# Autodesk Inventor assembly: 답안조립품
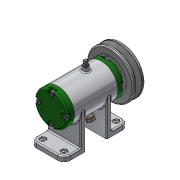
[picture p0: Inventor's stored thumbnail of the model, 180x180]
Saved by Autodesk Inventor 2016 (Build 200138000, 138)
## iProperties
Created: 2017-02
Part Number: 답안조립품
Material: 일반
Document SubType Name: Assembly
Designer: H
Author: H
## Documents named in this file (16)
- C:\Users\CAMTIC\Desktop\470207V1019\답안조립품.iam
- C:\Users\CAMTIC\Desktop\470207V1019\본체.ipt
- C:\Users\CAMTIC\Desktop\470207V1019\V벨트풀리.ipt
- C:\Users\CAMTIC\Desktop\470207V1019\너트 M 8.ipt
- C:\Users\CAMTIC\Desktop\470207V1019\니플 M 6 x 0.75.ipt
- C:\Users\CAMTIC\Desktop\470207V1019\뒤커버.ipt
- C:\Users\CAMTIC\Desktop\470207V1019\베어링 15 x 32 x 9.ipt
- C:\Users\CAMTIC\Desktop\470207V1019\볼트 M 6 x 8.ipt
- C:\Users\CAMTIC\Desktop\470207V1019\볼트 M4 x 12.ipt
- C:\Users\CAMTIC\Desktop\470207V1019\스프링와셔 8.ipt
- C:\Users\CAMTIC\Desktop\470207V1019\앞커버.ipt
- C:\Users\CAMTIC\Desktop\470207V1019\오일 실 15 25 7.ipt
- C:\Users\CAMTIC\Desktop\470207V1019\와셔 6x11.5.ipt
- C:\Users\CAMTIC\Desktop\470207V1019\와셔 8x17.ipt
- C:\Users\CAMTIC\Desktop\470207V1019\축.ipt
- C:\Users\CAMTIC\Desktop\470207V1019\키 3 x 3 x 12.ipt
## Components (11 placed, 3 different names)
1. V벨트풀리:1
2. KS B 2023 6002 - 15 x 32 x 9:1
3. KS B 2023 6002 - 15 x 32 x 9:2
4. ISO 4762 M4 x 12:2
5. ISO 4762 M4 x 12:1
6. ISO 4762 M4 x 12:3
7. ISO 4762 M4 x 12:4
8. ISO 4762 M4 x 12:5
9. ISO 4762 M4 x 12:6
10. ISO 4762 M4 x 12:7
11. ISO 4762 M4 x 12:8
